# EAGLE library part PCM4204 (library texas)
High-Performance 24-Bit, 216kHz Sampling Four-Channel Audio-to-Digital Converter Auto generated by make-symbol-device-package-bsdl.ulp Rev. 29 Source: http://focus.ti.com/lit/ds/symlink/pcm4204.pdf
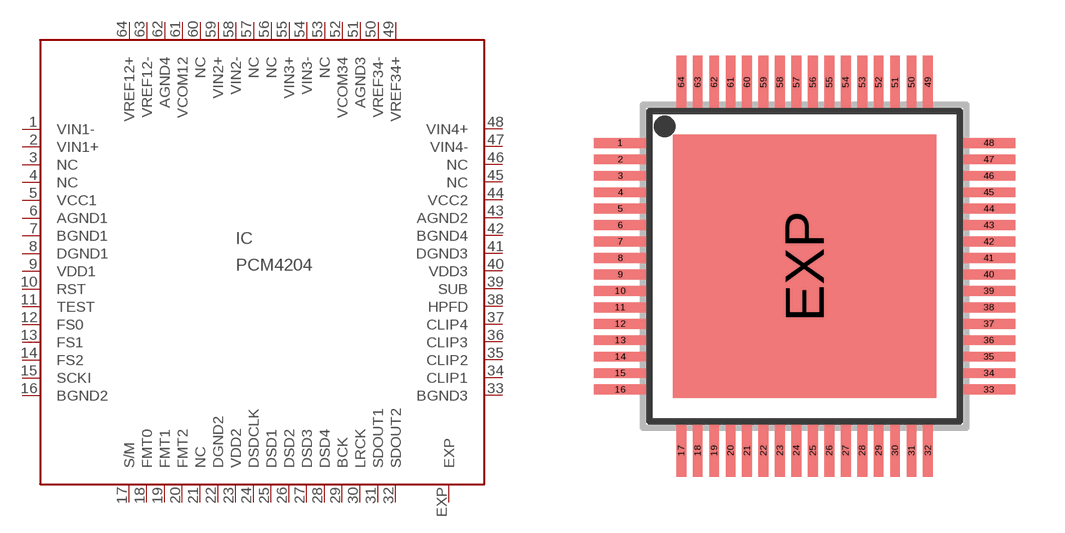
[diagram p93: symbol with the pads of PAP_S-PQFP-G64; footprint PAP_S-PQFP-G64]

Designator prefix IC

## PCM4204 (MF: TEXAS INSTRUMENTS; MPN: PCM4204PAPT; OC_FARNELL: 9969098; OC_NEWARK: 43J9723)  [PAP_S-PQFP-G64]
1  VIN1-  in
2  VIN1+  in
3  NC  nc
4  NC  nc
5  VCC1  pwr
6  AGND1  pwr
7  BGND1  pwr
8  DGND1  pwr
9  VDD1  pwr
10  RST  in
11  TEST  in
12  FS0  in
13  FS1  in
14  FS2  in
15  SCKI  in
16  BGND2  pwr
17  S/M  in
18  FMT0  in
19  FMT1  in
20  FMT2  in
21  NC  nc
22  DGND2  pwr
23  VDD2  pwr
24  DSDCLK
25  DSD1
26  DSD2
27  DSD3
28  DSD4
29  BCK
30  LRCK
31  SDOUT1  out
32  SDOUT2  out
33  BGND3  pwr
34  CLIP1  out
35  CLIP2  out
36  CLIP3  out
37  CLIP4  out
38  HPFD  in
39  SUB  in
40  VDD3  pwr
41  DGND3  pwr
42  BGND4  pwr
43  AGND2  pwr
44  VCC2  pwr
45  NC  nc
46  NC  nc
47  VIN4-  in
48  VIN4+  in
49  VREF34+  out
50  VREF34-  out
51  AGND3  out
52  VCOM34  out
53  NC  nc
54  VIN3-  in
55  VIN3+  in
56  NC  nc
57  NC  nc
58  VIN2-  in
59  VIN2+  in
60  NC  nc
61  VCOM12  out
62  AGND4  pwr
63  VREF12-  out
64  VREF12+  out
EXP  EXP  out

## Footprint PAP_S-PQFP-G64 (pad centres in mm)
PAP (S-PQFP-G64) PowerPAD (TM) Source: http://focus.ti.com/lit/ds/symlink/pcm4204.pdf
smd 1.6 x 0.3: 1 -5.6,3.75; 2 -5.6,3.25; 3 -5.6,2.75; 4 -5.6,2.25; 5 -5.6,1.75; 6 -5.6,1.25; 7 -5.6,0.75; 8 -5.6,0.25; 9 -5.6,-0.25; 10 -5.6,-0.75; 11 -5.6,-1.25; 12 -5.6,-1.75; 13 -5.6,-2.25; 14 -5.6,-2.75; 15 -5.6,-3.25; 16 -5.6,-3.75; 33 5.6,-3.75; 34 5.6,-3.25; 35 5.6,-2.75; 36 5.6,-2.25; 37 5.6,-1.75; 38 5.6,-1.25; 39 5.6,-0.75; 40 5.6,-0.25; 41 5.6,0.25; 42 5.6,0.75; 43 5.6,1.25; 44 5.6,1.75; 45 5.6,2.25; 46 5.6,2.75; 47 5.6,3.25; 48 5.6,3.75
smd 0.3 x 1.6: 17 -3.75,-5.6; 18 -3.25,-5.6; 19 -2.75,-5.6; 20 -2.25,-5.6; 21 -1.75,-5.6; 22 -1.25,-5.6; 23 -0.75,-5.6; 24 -0.25,-5.6; 25 0.25,-5.6; 26 0.75,-5.6; 27 1.25,-5.6; 28 1.75,-5.6; 29 2.25,-5.6; 30 2.75,-5.6; 31 3.25,-5.6; 32 3.75,-5.6; 49 3.75,5.6; 50 3.25,5.6; 51 2.75,5.6; 52 2.25,5.6; 53 1.75,5.6; 54 1.25,5.6; 55 0.75,5.6; 56 0.25,5.6; 57 -0.25,5.6; 58 -0.75,5.6; 59 -1.25,5.6; 60 -1.75,5.6; 61 -2.25,5.6; 62 -2.75,5.6; 63 -3.25,5.6; 64 -3.75,5.6
smd 8 x 8: EXP 0,0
